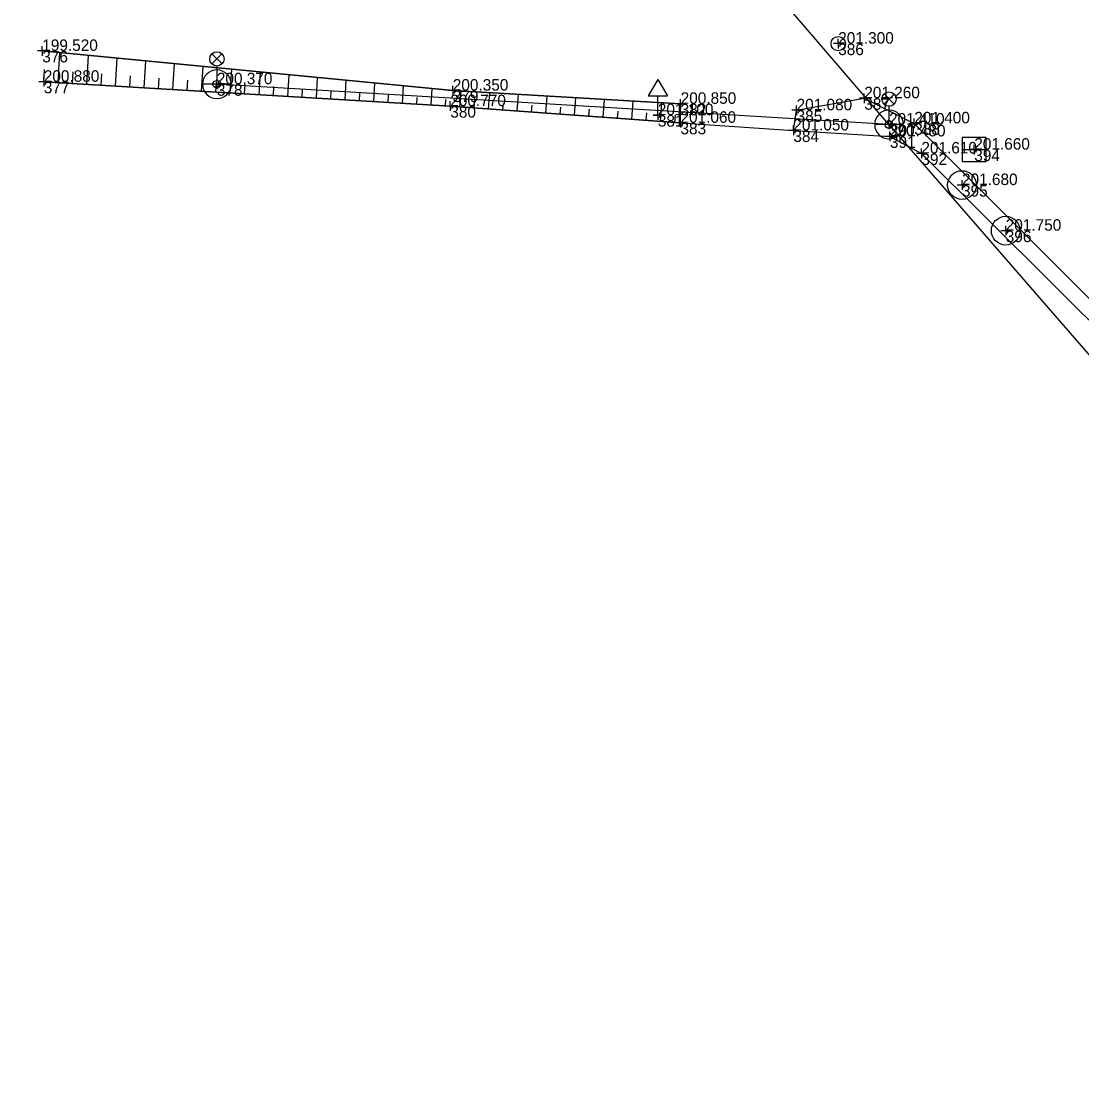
# Model space of a CAD drawing. Extents: x -744883 to -744469, y -966832 to -966374.
# Drawn here: x -744667.9 to -744612.5, y -966746.3 to -966691.4 of the extents above; entities that cross this region are included whole.
import ezdxf

# ---------------------------------------------------------------- set-up
doc = ezdxf.new("R2010")
doc.units = 0
for name, color, linetype in [('Body polohopisu', 7, 'Continuous'), ('Doplňkové značky', 7, 'Continuous'), ('Ploty_opěrné zdi', 7, 'Continuous'), ('Rozhraní ploch', 7, 'Continuous'), ('Vrstva 132', 7, 'Continuous'), ('Vstup na pozemek', 7, 'Continuous'), ('Výškopis', 7, 'Continuous'), ('Výšky bodů', 7, 'Continuous'), ('Značky IS', 7, 'Continuous'), ('Čísla bodů', 7, 'Continuous')]:
    doc.layers.add(name, color=color, linetype=linetype)

msp = doc.modelspace()

# ---------------------------------------------------------------- linework, layer by layer
at = {"layer": 'Body polohopisu'}
for p, q in [((-744666.78, -966692.98), (-744666.78, -966692.73)), ((-744625.25, -966692.6), (-744625.5, -966692.6)), ((-744625.25, -966692.6), (-744625.25, -966692.35)), ((-744625.25, -966692.6), (-744625, -966692.6)), ((-744625.25, -966692.6), (-744625.25, -966692.85)), ((-744666.78, -966692.98), (-744667.03, -966692.98)), ((-744666.78, -966692.98), (-744666.53, -966692.98)), ((-744666.78, -966692.98), (-744666.78, -966693.23)), ((-744666.7, -966694.59), (-744666.7, -966694.34)), ((-744666.7, -966694.59), (-744666.95, -966694.59)), ((-744666.7, -966694.59), (-744666.45, -966694.59)), ((-744666.7, -966694.59), (-744666.7, -966694.84)), ((-744657.67, -966694.72), (-744657.92, -966694.72)), ((-744657.67, -966694.72), (-744657.67, -966694.47)), ((-744657.67, -966694.72), (-744657.42, -966694.72)), ((-744657.67, -966694.72), (-744657.67, -966694.97)), ((-744645.36, -966695.05), (-744645.36, -966694.8)), ((-744645.36, -966695.05), (-744645.61, -966695.05)), ((-744645.36, -966695.05), (-744645.11, -966695.05)), ((-744645.36, -966695.05), (-744645.36, -966695.3)), ((-744633.47, -966695.74), (-744633.47, -966695.49)), ((-744623.89, -966695.45), (-744624.14, -966695.45)), ((-744623.89, -966695.45), (-744623.89, -966695.2)), ((-744623.89, -966695.45), (-744623.64, -966695.45)), ((-744623.89, -966695.45), (-744623.89, -966695.7)), ((-744645.49, -966695.86), (-744645.74, -966695.86)), ((-744645.49, -966695.86), (-744645.49, -966695.61)), ((-744645.49, -966695.86), (-744645.24, -966695.86)), ((-744645.49, -966695.86), (-744645.49, -966696.11)), ((-744634.66, -966696.33), (-744634.66, -966696.08)), ((-744633.47, -966695.74), (-744633.72, -966695.74)), ((-744633.47, -966695.74), (-744633.22, -966695.74)), ((-744633.47, -966695.74), (-744633.47, -966695.99)), ((-744627.42, -966696.08), (-744627.67, -966696.08)), ((-744627.42, -966696.08), (-744627.42, -966695.83)), ((-744627.42, -966696.08), (-744627.17, -966696.08)), ((-744627.42, -966696.08), (-744627.42, -966696.33)), ((-744634.66, -966696.33), (-744634.91, -966696.33)), ((-744634.66, -966696.33), (-744634.41, -966696.33)), ((-744634.66, -966696.33), (-744634.66, -966696.58)), ((-744633.48, -966696.73), (-744633.48, -966696.48)), ((-744622.6, -966696.82), (-744622.6, -966696.57)), ((-744621.28, -966696.76), (-744621.28, -966696.51)), ((-744633.48, -966696.73), (-744633.73, -966696.73)), ((-744633.48, -966696.73), (-744633.23, -966696.73)), ((-744633.48, -966696.73), (-744633.48, -966696.98)), ((-744627.59, -966697.13), (-744627.84, -966697.13)), ((-744627.59, -966697.13), (-744627.59, -966696.88)), ((-744627.59, -966697.13), (-744627.34, -966697.13)), ((-744627.59, -966697.13), (-744627.59, -966697.38)), ((-744622.6, -966696.82), (-744622.85, -966696.82)), ((-744622.6, -966696.82), (-744622.35, -966696.82)), ((-744622.6, -966696.82), (-744622.6, -966697.07)), ((-744622.55, -966697.44), (-744622.55, -966697.19)), ((-744621.28, -966696.76), (-744621.53, -966696.76)), ((-744621.28, -966696.76), (-744621.03, -966696.76)), ((-744621.28, -966696.76), (-744621.28, -966697.01)), ((-744622.55, -966697.44), (-744622.8, -966697.44)), ((-744622.55, -966697.44), (-744622.3, -966697.44)), ((-744622.55, -966697.44), (-744622.55, -966697.69)), ((-744620.91, -966698.33), (-744621.16, -966698.33)), ((-744620.91, -966698.33), (-744620.91, -966698.08)), ((-744620.91, -966698.33), (-744620.66, -966698.33)), ((-744620.91, -966698.33), (-744620.91, -966698.58)), ((-744618.15, -966698.13), (-744618.4, -966698.13)), ((-744618.15, -966698.13), (-744618.15, -966697.88)), ((-744618.15, -966698.13), (-744617.9, -966698.13)), ((-744618.15, -966698.13), (-744618.15, -966698.38)), ((-744618.79, -966699.98), (-744619.04, -966699.98)), ((-744618.79, -966699.98), (-744618.79, -966699.73)), ((-744618.79, -966699.98), (-744618.54, -966699.98)), ((-744618.79, -966699.98), (-744618.79, -966700.23)), ((-744616.51, -966702.36), (-744616.51, -966702.11)), ((-744616.51, -966702.36), (-744616.76, -966702.36)), ((-744616.51, -966702.36), (-744616.26, -966702.36)), ((-744616.51, -966702.36), (-744616.51, -966702.61))]:
    msp.add_line(p, q, dxfattribs=at)
at = {"layer": 'Doplňkové značky'}
for p, q in [((-744657.934, -966693.658), (-744657.406, -966693.13)), ((-744657.398, -966693.655), (-744657.926, -966693.126)), ((-744657.67, -966693.77), (-744657.67, -966694.52)), ((-744634.66, -966694.464), (-744635.16, -966695.33)), ((-744634.66, -966694.464), (-744634.16, -966695.33)), ((-744635.16, -966695.33), (-744634.16, -966695.33)), ((-744634.66, -966696.33), (-744634.66, -966695.33)), ((-744622.864, -966695.758), (-744622.336, -966695.23)), ((-744622.328, -966695.755), (-744622.856, -966695.226)), ((-744622.6, -966695.87), (-744622.6, -966696.62)), ((-744634.91, -966696.33), (-744634.41, -966696.33))]:
    msp.add_line(p, q, dxfattribs=at)
for centre, radius in [((-744657.67, -966693.395), 0.375), ((-744657.67, -966694.72), 0.2), ((-744622.6, -966695.495), 0.375), ((-744622.6, -966696.82), 0.2), ((-744618.79, -966699.98), 0.75), ((-744616.51, -966702.36), 0.75)]:
    msp.add_circle(centre, radius, dxfattribs=at)
at = {"layer": 'Ploty_opěrné zdi'}
for points in [[(-744633.48, -966696.73), (-744645.49, -966695.86), (-744666.7, -966694.59)], [(-744627.59, -966697.13), (-744622.55, -966697.44), (-744620.91, -966698.33), (-744610.75, -966708.44)]]:
    msp.add_lwpolyline(points, dxfattribs=at)
at = {"layer": 'Rozhraní ploch'}
for points in [[(-744633.48, -966696.73), (-744633.47, -966695.74), (-744645.36, -966695.05), (-744666.78, -966692.98)], [(-744627.59, -966697.13), (-744627.42, -966696.08), (-744623.89, -966695.45), (-744621.28, -966696.76), (-744621.28, -966696.76), (-744610.5, -966707.55), (-744607.28, -966710.23)]]:
    msp.add_lwpolyline(points, dxfattribs=at)
at = {"layer": 'Vrstva 132'}
for points in [[(-744622.6, -966696.82), (-744637.75, -966679.16), (-744667.44, -966651.83), (-744705.89, -966635.13)], [(-744622.6, -966696.82), (-744657.67, -966694.72)], [(-744622.6, -966696.82), (-744602.07, -966720.45), (-744591.37, -966746.3)]]:
    msp.add_lwpolyline(points, dxfattribs=at)
at = {"layer": 'Vstup na pozemek'}
msp.add_lwpolyline([(-744633.48, -966696.73), (-744627.59, -966697.13)], dxfattribs=at)
at = {"layer": 'Výškopis'}
for points in [[(-744666.78, -966692.98), (-744645.36, -966695.05), (-744633.47, -966695.74)], [(-744665.951, -966694.635), (-744665.858, -966693.069)], [(-744664.454, -966694.724), (-744664.364, -966693.214)], [(-744662.957, -966694.814), (-744662.87, -966693.358)], [(-744661.459, -966694.904), (-744661.375, -966693.502)], [(-744659.962, -966694.993), (-744659.881, -966693.647)], [(-744658.465, -966695.083), (-744658.387, -966693.791)], [(-744666.7, -966694.59), (-744666.662, -966693.953)], [(-744665.203, -966694.68), (-744665.166, -966694.064)], [(-744663.705, -966694.769), (-744663.67, -966694.176)], [(-744662.208, -966694.859), (-744662.174, -966694.287)], [(-744660.711, -966694.949), (-744660.678, -966694.399)], [(-744656.967, -966695.173), (-744656.893, -966693.935)], [(-744655.47, -966695.262), (-744655.399, -966694.08)], [(-744653.973, -966695.352), (-744653.905, -966694.224)], [(-744652.475, -966695.442), (-744652.411, -966694.369)], [(-744666.7, -966694.59), (-744645.49, -966695.86), (-744633.48, -966696.73)], [(-744659.213, -966695.038), (-744659.182, -966694.511)], [(-744657.716, -966695.128), (-744657.686, -966694.622)], [(-744656.219, -966695.218), (-744656.19, -966694.734)], [(-744654.721, -966695.307), (-744654.694, -966694.845)], [(-744653.224, -966695.397), (-744653.198, -966694.957)], [(-744650.978, -966695.531), (-744650.917, -966694.513)], [(-744649.481, -966695.621), (-744649.423, -966694.657)], [(-744647.984, -966695.711), (-744647.929, -966694.802)], [(-744646.486, -966695.8), (-744646.435, -966694.946)], [(-744651.727, -966695.487), (-744651.702, -966695.068)], [(-744650.229, -966695.576), (-744650.206, -966695.18)], [(-744648.732, -966695.666), (-744648.71, -966695.291)], [(-744647.235, -966695.756), (-744647.214, -966695.403)], [(-744645.738, -966695.845), (-744645.718, -966695.514)], [(-744644.989, -966695.896), (-744644.93, -966695.075)], [(-744643.493, -966696.005), (-744643.432, -966695.162)], [(-744641.997, -966696.113), (-744641.935, -966695.249)], [(-744640.501, -966696.221), (-744640.437, -966695.336)], [(-744639.005, -966696.33), (-744638.939, -966695.423)], [(-744637.509, -966696.438), (-744637.442, -966695.51)], [(-744644.241, -966695.95), (-744644.217, -966695.618)], [(-744642.745, -966696.059), (-744642.72, -966695.717)], [(-744641.249, -966696.167), (-744641.224, -966695.817)], [(-744639.753, -966696.276), (-744639.727, -966695.917)], [(-744638.257, -966696.384), (-744638.23, -966696.017)], [(-744636.761, -966696.492), (-744636.734, -966696.117)], [(-744636.013, -966696.547), (-744635.944, -966695.596)], [(-744634.517, -966696.655), (-744634.446, -966695.683)], [(-744635.265, -966696.601), (-744635.237, -966696.216)], [(-744633.769, -966696.709), (-744633.74, -966696.316)]]:
    msp.add_lwpolyline(points, dxfattribs=at)
at = {"layer": 'Značky IS'}
for p, q in [((-744656.922, -966694.72), (-744658.417, -966694.72)), ((-744621.853, -966696.82), (-744623.348, -966696.82)), ((-744618.775, -966698.13), (-744617.525, -966698.13))]:
    msp.add_line(p, q, dxfattribs=at)
msp.add_lwpolyline([(-744618.775, -966698.757), (-744617.524, -966698.757), (-744617.524, -966697.503), (-744618.775, -966697.503)], close=True, dxfattribs=at)
msp.add_circle((-744625.25, -966692.6), 0.375, dxfattribs=at)
for centre, start, end in [((-744657.67, -966694.72), 0, 180), ((-744657.67, -966694.72), 180, 0), ((-744622.6, -966696.82), 0, 180), ((-744622.6, -966696.82), 180, 0)]:
    msp.add_arc(centre, 0.747, start, end, dxfattribs=at)

# ---------------------------------------------------------------- texts
at = {"layer": 'Výšky bodů'}
for s, p in [('201.300', (-744625.25, -966692.6)), ('199.520', (-744666.78, -966692.98)), ('200.880', (-744666.7, -966694.59)), ('200.370', (-744657.67, -966694.72)), ('200.350', (-744645.36, -966695.05)), ('201.260', (-744623.89, -966695.45)), ('200.770', (-744645.49, -966695.86)), ('200.850', (-744633.47, -966695.74)), ('201.080', (-744627.42, -966696.08)), ('201.100', (-744634.66, -966696.33)), ('201.060', (-744633.48, -966696.73)), ('201.050', (-744627.59, -966697.13)), ('201.410', (-744622.6, -966696.82)), ('201.400', (-744621.28, -966696.76)), ('201.480', (-744622.55, -966697.44)), ('201.610', (-744620.91, -966698.33)), ('201.660', (-744618.15, -966698.13)), ('201.680', (-744618.79, -966699.98)), ('201.750', (-744616.51, -966702.36))]:
    msp.add_text(s, height=0.6, dxfattribs=at).set_placement(p)
at = {"layer": 'Čísla bodů'}
for s, p in [('386', (-744625.25, -966693.2)), ('376', (-744666.78, -966693.58)), ('377', (-744666.7, -966695.19)), ('378', (-744657.67, -966695.32)), ('379', (-744645.36, -966695.65)), ('387', (-744623.89, -966696.05)), ('380', (-744645.49, -966696.46)), ('382', (-744633.47, -966696.34)), ('385', (-744627.42, -966696.68)), ('381', (-744634.66, -966696.93)), ('383', (-744633.48, -966697.33)), ('384', (-744627.59, -966697.73)), ('390', (-744622.6, -966697.42)), ('388', (-744621.28, -966697.36)), ('391', (-744622.55, -966698.04)), ('392', (-744620.91, -966698.93)), ('394', (-744618.15, -966698.73)), ('395', (-744618.79, -966700.58)), ('396', (-744616.51, -966702.96))]:
    msp.add_text(s, height=0.6, dxfattribs=at).set_placement(p)

doc.saveas('drawing.dxf')
